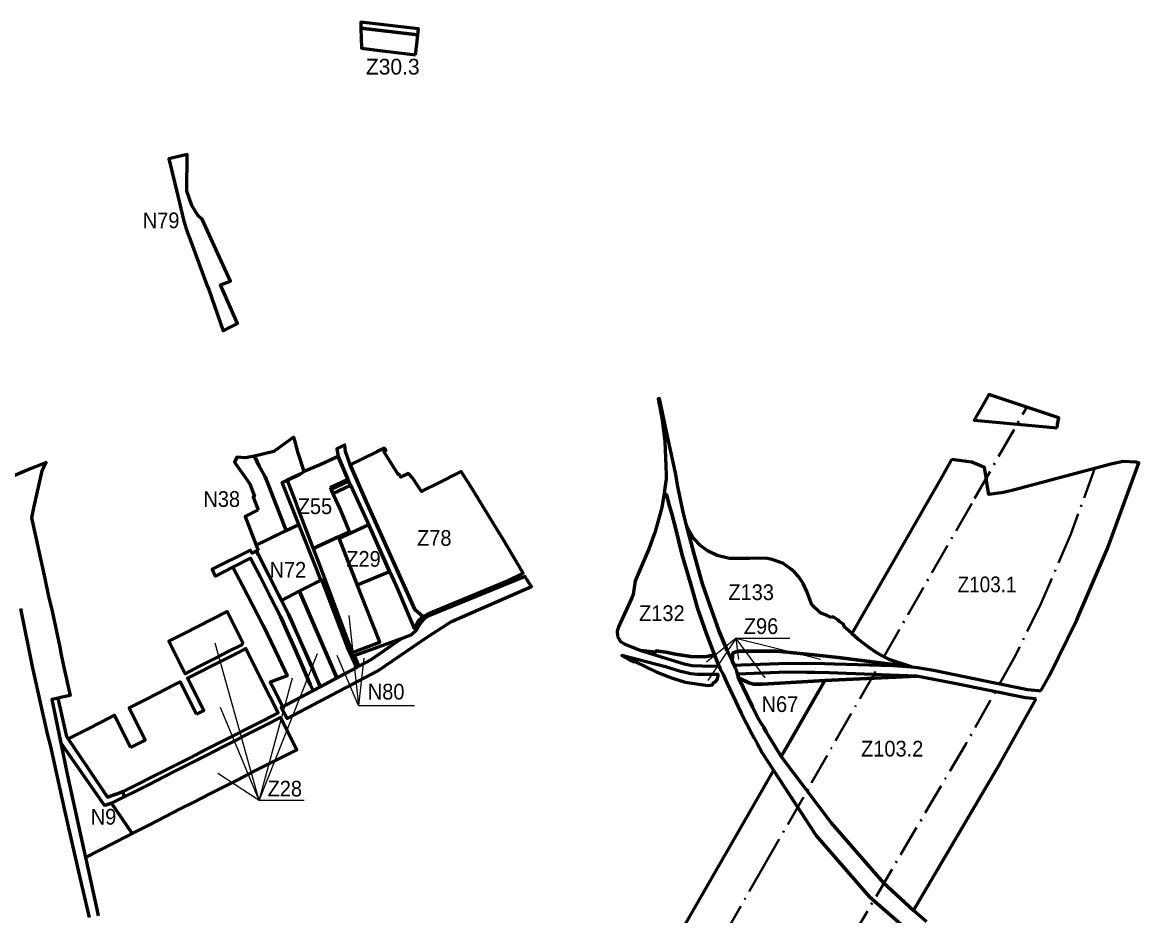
# Model space of a CAD drawing. Extents: x -650277 to -643422, y -1073980 to -1066720.
# Drawn here: x -648765 to -647061, y -1068122 to -1066758 of the extents above; entities that cross this region are included whole.
import ezdxf

# ---------------------------------------------------------------- set-up
doc = ezdxf.new("R2010")
doc.units = 0
doc.header["$LTSCALE"] = 9.6
doc.linetypes.add('DOT_DASHED', pattern=[7.7, 5, -1.2, 0.3, -1.2])
for name, color, linetype, lineweight in [('1', 7, 'Continuous', 60), ('15', 7, 'Continuous', 60), ('3', 7, 'Continuous', 60), ('40', 7, 'Continuous', 60), ('42', 7, 'Continuous', 60), ('45', 7, 'Continuous', 60), ('48', 7, 'Continuous', 60), ('60', 7, 'Continuous', 60), ('61', 7, 'Continuous', 60), ('62', 7, 'DOT_DASHED', 40), ('63', 7, 'Continuous', 25), ('7', 7, 'Continuous', 60), ('9', 7, 'Continuous', 60)]:
    doc.layers.add(name, color=color, linetype=linetype, lineweight=lineweight)

msp = doc.modelspace()

# ---------------------------------------------------------------- linework, layer by layer
at = {"layer": '1'}
msp.add_line((-648609.91, -1067940.58), (-648611.61, -1067932.63), dxfattribs=at)
for points in [[(-647708.71, -1067723.99), (-647721.05, -1067691.73), (-647734.63, -1067652.57), (-647744.61, -1067617.96), (-647758.25, -1067571.79), (-647768.5, -1067529.75), (-647773.96, -1067508.48), (-647777.55, -1067496.95), (-647781.85, -1067479.19), (-647785.64, -1067477.02), (-647789.39, -1067498.84), (-647792.54, -1067511.85), (-647799.39, -1067535.48)], [(-647704.458, -1067572.034), (-647719.661, -1067564.884), (-647729.802, -1067557.462), (-647740.124, -1067546.265), (-647751.41, -1067526.58), (-647740.49, -1067568.67), (-647727.37, -1067614.33), (-647715.92, -1067648.12), (-647702.04, -1067686.86), (-647690.09, -1067716.05), (-647681.91, -1067732.74), (-647680.804, -1067720.745), (-647672, -1067718), (-647643, -1067718), (-647614, -1067718), (-647557, -1067724), (-647520.145, -1067727.879), (-647408.2, -1067742.37)], [(-647799.39, -1067535.48), (-647808.71, -1067561.03), (-647817.59, -1067582.4)], [(-647591.227, -1067593.613), (-647604.415, -1067584.047), (-647606.559, -1067583.309), (-647620.586, -1067578.478), (-647628.441, -1067576.759), (-647640.087, -1067576.306), (-647654.743, -1067576.996), (-647685.968, -1067576.68), (-647704.458, -1067572.034)], [(-647817.59, -1067582.4), (-647829.97, -1067610.62), (-647832.8, -1067631.53), (-647835.06, -1067637.01), (-647855.24, -1067681.26), (-647857.51, -1067687.74), (-647856.9, -1067695.97)], [(-647573.605, -1067614.951), (-647580.539, -1067604.432), (-647586.864, -1067597.411), (-647591.227, -1067593.613)], [(-647530.82, -1067666.65), (-647536.83, -1067663.64), (-647547.663, -1067659.519), (-647560.187, -1067647.458), (-647567.744, -1067627.24), (-647573.605, -1067614.951)], [(-647499.095, -1067691.163), (-647503.97, -1067686.73), (-647510.6, -1067680.86), (-647511.24, -1067677.53), (-647517.74, -1067672.85), (-647520.13, -1067671.13), (-647527.76, -1067665.65), (-647530.82, -1067666.65)], [(-647856.9, -1067695.97), (-647852.3, -1067703.36), (-647845.74, -1067707.59), (-647821.02, -1067717.33)], [(-647474.13, -1067711.81), (-647489.3, -1067700.07), (-647499.095, -1067691.163)], [(-648399.64, -1067763.26), (-648424.14, -1067714.34), (-648435.34, -1067720.01), (-648446.58, -1067725.71), (-648468.97, -1067736.91), (-648480.06, -1067742.47), (-648491.14, -1067748.02), (-648513.23, -1067759.38), (-648488.49, -1067808.76), (-648499.7, -1067814.37)], [(-647453.87, -1067724.97), (-647462.45, -1067719.84), (-647474.13, -1067711.81)], [(-647821.02, -1067717.33), (-647798.5, -1067719.67), (-647798.17, -1067717.58), (-647783.13, -1067719.68), (-647768.53, -1067722.82), (-647745.41, -1067726.6), (-647732.71, -1067727.02), (-647720.45, -1067726.49), (-647708.71, -1067723.99)], [(-647408.2, -1067742.37), (-647440.81, -1067731.38), (-647453.87, -1067724.97)], [(-648611.61, -1067932.63), (-648547.09, -1067899.87), (-648530.81, -1067891.61), (-648508.22, -1067880.38), (-648486.09, -1067868.98), (-648463.91, -1067857.74), (-648441.47, -1067846.37), (-648419.44, -1067835.3), (-648397.04, -1067823.85), (-648374.84, -1067812.43), (-648399.64, -1067763.26)], [(-648499.7, -1067814.37), (-648524.44, -1067765.11), (-648535.61, -1067770.85), (-648557.84, -1067782.26), (-648580.14, -1067793.61), (-648602.3, -1067804.83), (-648577.78, -1067854.07), (-648600.14, -1067865.29)], [(-648600.14, -1067865.29), (-648624.76, -1067816.11), (-648645.11, -1067826.48), (-648668.085, -1067838.186), (-648675.26, -1067841.84), (-648695.27, -1067852.04), (-648664.41, -1067897.91)], [(-648572.5, -1067983.59), (-648546.76, -1067970.44), (-648524.72, -1067958.93), (-648502.59, -1067948), (-648480.12, -1067936.55), (-648457.87, -1067925.4), (-648435.55, -1067913.84), (-648413.41, -1067902.53), (-648402.29, -1067897.02), (-648391.08, -1067891.24), (-648368.78, -1067879.75), (-648346.57, -1067868.56), (-648371.27, -1067819.47), (-648393.35, -1067830.81), (-648415.69, -1067841.98), (-648426.65, -1067847.64), (-648437.89, -1067853.4), (-648460.33, -1067864.88), (-648482.5, -1067876.22), (-648504.92, -1067887.52), (-648527.33, -1067898.74), (-648549.44, -1067910.07), (-648571.88, -1067921.71), (-648591.04, -1067931.62), (-648609.91, -1067940.58)], [(-648664.41, -1067897.91), (-648635.249, -1067941.252), (-648620.658, -1067935.93), (-648611.61, -1067932.63)], [(-648609.91, -1067940.58), (-648629.22, -1067950.214), (-648597.93, -1067996.72), (-648572.5, -1067983.59)]]:
    msp.add_lwpolyline(points, dxfattribs=at)
for points in [[(-648254.04, -1067616.96), (-648204.88, -1067596.54), (-648236.549, -1067525.258), (-648263.7, -1067537.93), (-648281.774, -1067546.369)], [(-648397.98, -1067678.79), (-648373.99, -1067728.95), (-648361.08, -1067755.88), (-648387.04, -1067765.67), (-648384.25, -1067771.07), (-648367.811, -1067802.994), (-648321.623, -1067778.399), (-648326, -1067769), (-648337.32, -1067742.59), (-648348.55, -1067716.71), (-648359.6, -1067691.58), (-648371.34, -1067665.08), (-648386.91, -1067634.83), (-648402.02, -1067605.49), (-648417.12, -1067576.17), (-648443.83, -1067589.92), (-648428.7, -1067619.24), (-648413.57, -1067648.57)], [(-648342.697, -1067626.806), (-648369.949, -1067640.851), (-648359.213, -1067661.956), (-648310.511, -1067772.476), (-648285.254, -1067759.008), (-648296.891, -1067732.172), (-648342.023, -1067628.096)], [(-648519.63, -1067691.58), (-648541.86, -1067702.86), (-648516.73, -1067752.57), (-648494.84, -1067741.06), (-648472.5, -1067729.76), (-648450.23, -1067718.32), (-648430.17, -1067708.33), (-648428.67, -1067705.52), (-648452.72, -1067657.62)]]:
    msp.add_lwpolyline(points, close=True, dxfattribs=at)
at = {"layer": '1', "lineweight": 25}
msp.add_lwpolyline([(-648335, -1067946), (-648404, -1067946), (-648353, -1067759)], dxfattribs=at)
at = {"layer": '15'}
msp.add_line((-648264.34, -1067464.83), (-648267.21, -1067458.61), dxfattribs=at)
for points in [[(-648161.58, -1066777.41), (-648160.51, -1066768.4), (-648248.43, -1066758.34), (-648248.77, -1066767.43)], [(-648362.585, -1067534.204), (-648343.41, -1067524.81), (-648369.01, -1067460.52), (-648361, -1067457.36), (-648341.15, -1067448.14), (-648335.38, -1067444.07), (-648344.41, -1067416.04), (-648349.67, -1067396.88), (-648351.06, -1067391.62), (-648352.16, -1067392.42), (-648353.35, -1067393.29), (-648381.48, -1067413.68), (-648410.92, -1067420.63), (-648409.61, -1067423.44), (-648404.29, -1067434.9), (-648394.92, -1067452.23), (-648393.17, -1067455.88)], [(-648237.81, -1067522.42), (-648204.88, -1067596.54), (-648198.39, -1067610.97), (-648193.8, -1067621), (-648189.03, -1067631.71), (-648167.48, -1067683.45), (-648164.79, -1067678.96), (-648163.11, -1067676.17), (-648160.68, -1067671.55), (-648153.98, -1067665.43), (-648166.173, -1067654.853), (-648240.51, -1067489.9), (-648265.197, -1067434.03), (-648265.197, -1067434.03), (-648272.022, -1067413.59), (-648273.008, -1067403.338), (-648279.24, -1067406.38), (-648285.08, -1067409.24), (-648283.21, -1067420.88), (-648268.67, -1067455.43), (-648267.21, -1067458.61), (-648294.04, -1067471.35), (-648291.172, -1067477.571), (-648264.34, -1067464.83), (-648253.1, -1067489.23)], [(-648359.6, -1067691.58), (-648348.55, -1067716.71), (-648337.32, -1067742.59), (-648326, -1067769), (-648321.623, -1067778.399), (-648310.511, -1067772.476), (-648323.178, -1067741.953), (-648359.213, -1067661.956), (-648405.054, -1067571.837), (-648408.002, -1067565.219), (-648414.73, -1067568.8), (-648417.19, -1067564.02), (-648475.78, -1067593.11), (-648473.34, -1067598.06), (-648470.57, -1067603.69), (-648470.47, -1067603.64), (-648443.83, -1067589.92), (-648417.12, -1067576.17), (-648402.02, -1067605.49), (-648386.91, -1067634.83), (-648371.34, -1067665.08)], [(-647988.235, -1067619.912), (-647995.04, -1067608.56), (-647997.68, -1067604.11), (-648144.83, -1067664.48), (-648151.6, -1067668.12), (-648157.2, -1067674.32), (-648161, -1067680.96), (-648162.69, -1067684), (-648164.09, -1067686.51), (-648171.21, -1067693.37), (-648187.139, -1067699.179), (-648233.264, -1067731.288), (-648251.711, -1067741.124), (-648258.96, -1067725.37), (-648262.632, -1067726.711), (-648255.016, -1067742.886), (-648319.983, -1067777.526), (-648370.113, -1067804.22), (-648360.993, -1067821.027), (-648222.872, -1067748.412), (-648146.127, -1067695.8), (-648110.36, -1067673.133), (-647988.052, -1067619.624)]]:
    msp.add_lwpolyline(points, close=True, dxfattribs=at)
for points in [[(-648793.71, -1067456.88), (-648757.97, -1067441.51), (-648728.95, -1067430.33), (-648735.59, -1067442.88), (-648748.53, -1067499.3), (-648751.29, -1067514.57), (-648731.06, -1067607.06), (-648725.8, -1067632.36), (-648720.1, -1067657.12), (-648708.26, -1067712.07), (-648706.08, -1067723.56), (-648702.33, -1067740.84), (-648692.53, -1067785.79), (-648704.614, -1067788.491), (-648710.961, -1067789.906), (-648720.34, -1067792), (-648696.93, -1067905.76), (-648672.31, -1068017.25), (-648668.92, -1068032.96), (-648651.89, -1068111.95), (-648649.74, -1068121.95)], [(-648267.21, -1067458.61), (-648294.04, -1067471.35), (-648291.172, -1067477.571), (-648264.34, -1067464.83)], [(-648662.71, -1068124.76), (-648677.61, -1068061.74), (-648700.16, -1067963.42), (-648722.09, -1067863.84), (-648727.05, -1067844.33), (-648738.7, -1067792.04), (-648749.97, -1067741.49), (-648767.84, -1067652.98)], [(-648710.961, -1067789.906), (-648720.34, -1067792), (-648706.687, -1067858.345), (-648640, -1067954)], [(-648695.27, -1067852.04), (-648697.7, -1067848.43), (-648699.621, -1067840.06), (-648699.593, -1067840.046), (-648710.96, -1067789.91)], [(-648611.61, -1067932.63), (-648620.658, -1067935.93), (-648635.249, -1067941.252), (-648664.41, -1067897.91), (-648695.27, -1067852.04)], [(-648640, -1067954), (-648629.22, -1067950.214), (-648609.91, -1067940.58), (-648611.61, -1067932.63)]]:
    msp.add_lwpolyline(points, dxfattribs=at)
at = {"layer": '3'}
msp.add_lwpolyline([(-648165.33, -1066807.74), (-648162.8, -1066786.8), (-648161.58, -1066777.41), (-648248.77, -1066767.43), (-648247.78, -1066797.53), (-648211.58, -1066802.18)], close=True, dxfattribs=at)
at = {"layer": '40'}
msp.add_lwpolyline([(-648405.27, -1067502.27), (-648425.5, -1067512.73), (-648408.26, -1067556.58), (-648362.585, -1067534.205), (-648393.17, -1067455.88), (-648394.92, -1067452.23), (-648404.29, -1067434.9), (-648410.92, -1067420.63), (-648425, -1067423.05), (-648437.75, -1067421.99), (-648441.48, -1067429.63), (-648430.4, -1067445.51), (-648418.3, -1067462.86), (-648412.46, -1067477.42), (-648411.25, -1067481.73), (-648412.89, -1067482.55)], close=True, dxfattribs=at)
at = {"layer": '42'}
msp.add_lwpolyline([(-647606.818, -1067879.061), (-647540.208, -1067762.876), (-647635.758, -1067768.38), (-647649.22, -1067768.38), (-647656.469, -1067766.309), (-647672.05, -1067758.98), (-647650.8, -1067803.28), (-647642.29, -1067820.76), (-647637.21, -1067829.29), (-647633.69, -1067834.31), (-647630.3, -1067841.02), (-647625.37, -1067848.86), (-647617.25, -1067861.95)], close=True, dxfattribs=at)
at = {"layer": '45'}
msp.add_lwpolyline([(-648405.41, -1067563.84), (-648408.002, -1067565.219), (-648369.949, -1067640.851), (-648342.697, -1067626.806), (-648328.54, -1067619.51), (-648309.522, -1067609.713), (-648317.43, -1067590), (-648343.41, -1067524.81), (-648408.26, -1067556.58)], close=True, dxfattribs=at)
at = {"layer": '48'}
for points in [[(-648528.01, -1067023.13), (-648518.72, -1067061.99), (-648514.86, -1067074.83), (-648507.88, -1067093.9), (-648483.31, -1067160.63), (-648480.57, -1067166.13), (-648458.73, -1067229.1), (-648449.03, -1067224.14), (-648437.02, -1067217.99), (-648462.97, -1067159.24), (-648447.66, -1067153.25), (-648467.56, -1067110.02), (-648490.23, -1067060.06), (-648496.87, -1067053.5), (-648506.78, -1067037.81), (-648514.38, -1067016.2), (-648513.842, -1066960.243), (-648541.52, -1066966.657)], [(-648342.023, -1067628.096), (-648296.891, -1067732.172), (-648285.254, -1067759.008), (-648255.016, -1067742.886), (-648265.614, -1067720.378), (-648269.27, -1067712.6), (-648308.43, -1067609.15), (-648328.54, -1067619.51), (-648342.697, -1067626.806)], [(-648258.96, -1067725.37), (-648251.711, -1067741.124), (-648233.264, -1067731.288), (-648187.139, -1067699.179)]]:
    msp.add_lwpolyline(points, close=True, dxfattribs=at)
for points in [[(-648295.409, -1067468.129), (-648268.67, -1067455.43), (-648283.21, -1067420.88), (-648295.66, -1067426.76), (-648309.57, -1067433.34), (-648335.38, -1067444.07), (-648341.15, -1067448.14), (-648361, -1067457.36), (-648347.51, -1067492.87), (-648346.27, -1067496.14)], [(-648346.27, -1067496.14), (-648334.09, -1067528.2), (-648321.36, -1067561.69), (-648282.863, -1067543.596), (-648265.757, -1067535.555), (-648279.86, -1067502.11), (-648294.04, -1067471.35), (-648295.409, -1067468.129)], [(-648265.08, -1067712.06), (-648261.25, -1067720.39), (-648235.78, -1067710.79), (-648219.86, -1067704.42), (-648247.53, -1067633.53), (-648254.04, -1067616.96), (-648282.863, -1067543.596), (-648321.36, -1067561.69)], [(-648321.361, -1067561.69), (-648311.95, -1067586.45), (-648265.08, -1067712.06)]]:
    msp.add_lwpolyline(points, dxfattribs=at)
at = {"layer": '60'}
for points in [[(-647606.818, -1067879.061), (-647617.25, -1067861.95), (-647625.37, -1067848.86), (-647630.3, -1067841.02), (-647633.69, -1067834.31), (-647637.21, -1067829.29), (-647642.29, -1067820.76), (-647650.8, -1067803.28), (-647672.05, -1067758.98), (-647673.47, -1067753.48), (-647673.47, -1067753.48), (-647674.67, -1067748.73), (-647676.47, -1067744.5), (-647678.66, -1067739.38), (-647681.91, -1067732.74), (-647690.09, -1067716.05), (-647702.04, -1067686.86), (-647715.92, -1067648.12), (-647727.37, -1067614.33), (-647740.49, -1067568.67), (-647751.41, -1067526.58), (-647756.55, -1067505.32), (-647759.16, -1067494.01), (-647764.89, -1067466.64), (-647768.5, -1067446.04), (-647778.78, -1067397.1), (-647792.52, -1067332.74), (-647794.54, -1067333.14), (-647788.77, -1067365.03), (-647784.55, -1067398.01), (-647782.39, -1067448.34), (-647782.5, -1067455.11), (-647784.36, -1067469.6), (-647785.64, -1067477.02), (-647781.85, -1067479.19), (-647777.55, -1067496.95), (-647773.96, -1067508.48), (-647768.5, -1067529.75), (-647758.25, -1067571.79), (-647744.61, -1067617.96), (-647734.63, -1067652.57), (-647721.05, -1067691.73), (-647708.71, -1067723.99), (-647702.21, -1067740.43), (-647699.89, -1067745.24), (-647697.85, -1067749.46), (-647695.71, -1067753.9), (-647690.19, -1067766.37), (-647668.13, -1067812.76), (-647651.94, -1067844.36), (-647648.33, -1067851.17), (-647643.83, -1067859.13), (-647635.77, -1067873.43), (-647618.773, -1067899.914)], [(-647783.54, -1067742.11), (-647850.45, -1067724.77), (-647838.18, -1067731.62), (-647832.56, -1067734.22), (-647829.49, -1067734.58), (-647796.87, -1067750.25), (-647774.54, -1067758.68), (-647753.53, -1067765.58), (-647718.54, -1067770.6), (-647712.01, -1067769.63), (-647712.26, -1067767.28)], [(-647712.26, -1067767.28), (-647711.773, -1067767.135), (-647711.286, -1067766.968), (-647710.799, -1067766.777), (-647710.315, -1067766.562), (-647709.834, -1067766.324), (-647709.359, -1067766.062), (-647708.892, -1067765.776), (-647708.433, -1067765.466), (-647707.985, -1067765.133), (-647707.55, -1067764.777), (-647707.128, -1067764.398), (-647706.723, -1067763.999), (-647706.335, -1067763.579), (-647705.966, -1067763.14), (-647705.617, -1067762.683), (-647705.29, -1067762.21), (-647704.985, -1067761.721), (-647704.704, -1067761.22), (-647704.447, -1067760.707), (-647704.216, -1067760.184), (-647704.01, -1067759.653), (-647703.83, -1067759.117), (-647703.675, -1067758.576), (-647703.547, -1067758.033), (-647703.445, -1067757.489), (-647703.368, -1067756.946), (-647703.315, -1067756.406), (-647703.287, -1067755.87), (-647703.282, -1067755.341), (-647703.3, -1067754.818), (-647703.34, -1067754.304), (-647703.4, -1067753.8), (-647711.09, -1067753.71), (-647728.98, -1067754.07), (-647734.69, -1067753.66), (-647744.74, -1067752.93), (-647757.74, -1067749.96), (-647759.13, -1067749.54), (-647783.54, -1067742.11)], [(-647405.026, -1068113.904), (-647451.024, -1068071.886), (-647530.038, -1067980.839), (-647606.818, -1067879.061)], [(-647618.773, -1067899.914), (-647553.628, -1067999.427), (-647472.338, -1068093.096), (-647419.713, -1068138.871)], [(-647385.13, -1068131.51), (-647405.026, -1068113.904)]]:
    msp.add_lwpolyline(points, dxfattribs=at)
for points in [[(-647754.88, -1067737.59), (-647743.12, -1067739.93), (-647728.29, -1067740.64), (-647713.15, -1067741), (-647702.21, -1067740.43), (-647708.71, -1067723.99), (-647720.45, -1067726.49), (-647732.71, -1067727.02), (-647745.41, -1067726.6), (-647768.53, -1067722.82), (-647783.13, -1067719.68), (-647798.17, -1067717.58), (-647798.5, -1067719.67), (-647821.02, -1067717.33)], [(-647596.91, -1067736.61), (-647572.33, -1067737.03), (-647555.58, -1067736.71), (-647525.685, -1067737.542), (-647436.72, -1067740.02), (-647408.2, -1067742.37), (-647520.145, -1067727.879), (-647557, -1067724), (-647614, -1067718), (-647643, -1067718), (-647672, -1067718), (-647680.804, -1067720.745), (-647681.91, -1067732.74), (-647678.66, -1067739.38), (-647678.66, -1067739.38), (-647667.76, -1067739.01), (-647638.75, -1067738.03)], [(-647540.208, -1067762.876), (-647400.63, -1067756.19), (-647533.597, -1067751.344), (-647555.67, -1067750.91), (-647568.36, -1067750.7), (-647597.83, -1067750.21), (-647673.47, -1067753.48), (-647672.05, -1067758.98), (-647672.05, -1067758.98), (-647656.469, -1067766.309), (-647649.22, -1067768.38), (-647635.758, -1067768.38)]]:
    msp.add_lwpolyline(points, close=True, dxfattribs=at)
at = {"layer": '61'}
msp.add_lwpolyline([(-647185.93, -1067377.38), (-647184.97, -1067372.22), (-647183.09, -1067362.16), (-647289.924, -1067326.309), (-647312.383, -1067365.484)], close=True, dxfattribs=at)
for points in [[(-647346.944, -1067425.768), (-647364.024, -1067455.561), (-647499.095, -1067691.163), (-647489.3, -1067700.07)], [(-647243.39, -1067469.81), (-647252.99, -1067472.35), (-647267.49, -1067476.23), (-647290.23, -1067478.89), (-647292.51, -1067464.56), (-647294.31, -1067453.26), (-647296.75, -1067437.91), (-647315.89, -1067429.71), (-647346.944, -1067425.768)], [(-647061.252, -1067430.908), (-647061.252, -1067430.908), (-647063.45, -1067430.19), (-647064.87, -1067429.73), (-647084.77, -1067428.64), (-647103.55, -1067432.54), (-647243.39, -1067469.81)], [(-647210.537, -1067778.594), (-647198.088, -1067756.5), (-647155.592, -1067670.17), (-647108.971, -1067561.55), (-647061.252, -1067430.908)], [(-647489.3, -1067700.07), (-647474.13, -1067711.81), (-647462.45, -1067719.84), (-647453.87, -1067724.97), (-647440.81, -1067731.38), (-647408.2, -1067742.37), (-647398.74, -1067743.15), (-647374.55, -1067747.34)], [(-647374.55, -1067747.34), (-647280.78, -1067766.44), (-647237.91, -1067775.18), (-647231.17, -1067776.55), (-647213.92, -1067778.26), (-647210.537, -1067778.594)], [(-647400.63, -1067756.19), (-647540.208, -1067762.876), (-647593.267, -1067855.425), (-647606.818, -1067879.061)], [(-647217.611, -1067791.149), (-647233.83, -1067789.69), (-647345.11, -1067767.28), (-647400.63, -1067756.19)], [(-647405.026, -1068113.904), (-647273.297, -1067889.981), (-647217.611, -1067791.149)], [(-647606.818, -1067879.061), (-647530.038, -1067980.839), (-647451.024, -1068071.886), (-647405.026, -1068113.904)], [(-647464.94, -1068215.752), (-647461.188, -1068209.373), (-647419.713, -1068138.871), (-647472.338, -1068093.096), (-647553.628, -1067999.427), (-647618.773, -1067899.914), (-647685.819, -1068016.861)], [(-647685.819, -1068016.861), (-647781.346, -1068183.485), (-647791.055, -1068200.507)]]:
    msp.add_lwpolyline(points, dxfattribs=at)
at = {"layer": '62'}
for points in [[(-647729.261, -1068213.27), (-647633.767, -1068046.703), (-647560.654, -1067919.174), (-647311.972, -1067485.403), (-647231.921, -1067345.773)], [(-647128.118, -1067439.088), (-647164.761, -1067539.408), (-647210.113, -1067645.071), (-647251.182, -1067728.502), (-647325.296, -1067860.04), (-647512.903, -1068178.95), (-647726.877, -1068542.68), (-647850.594, -1068756.441), (-647875.691, -1068807.609), (-647903.473, -1068876.174), (-647924.037, -1068940.973), (-647945.559, -1069039.601), (-647956.348, -1069145.994), (-647956.677, -1069214.977), (-647954.925, -1069248.93), (-647950.785, -1069292.731), (-647945.699, -1069329.377), (-647937.748, -1069374.683)]]:
    msp.add_lwpolyline(points, dxfattribs=at)
at = {"layer": '63'}
for p, q in [((-648404, -1067946), (-648471, -1067706)), ((-647676, -1067699), (-647672, -1067731)), ((-647676, -1067699), (-647632, -1067759)), ((-648404, -1067946), (-648315, -1067722)), ((-648404, -1067946), (-648463, -1067804))]:
    msp.add_line(p, q, dxfattribs=at)
for points in [[(-648267, -1067664), (-648252, -1067801), (-648285, -1067725)], [(-647594, -1067699), (-647676, -1067699), (-647721, -1067735)], [(-647547, -1067731), (-647676, -1067699), (-647719, -1067763)], [(-648244, -1067729), (-648252, -1067801), (-648167, -1067801)], [(-648335, -1067946), (-648404, -1067946), (-648467, -1067905)]]:
    msp.add_lwpolyline(points, dxfattribs=at)
at = {"layer": '7'}
msp.add_lwpolyline([(-648640, -1067954), (-648706.687, -1067858.345), (-648696.93, -1067905.76), (-648668.92, -1068032.96), (-648605.323, -1068000.463), (-648597.93, -1067996.72), (-648629.22, -1067950.214)], close=True, dxfattribs=at)
at = {"layer": '9'}
msp.add_lwpolyline([(-648153.98, -1067665.43), (-648149.933, -1067663.646), (-648146.21, -1067661.3), (-648023.96, -1067610.13), (-648000.63, -1067599.14), (-648031.77, -1067546.6), (-648045.04, -1067525.15), (-648076.32, -1067474.6), (-648081.31, -1067466.54), (-648095.28, -1067444.06), (-648133.56, -1067463.2), (-648150.46, -1067471.66), (-648155.85, -1067474.35), (-648164.24, -1067462.15), (-648166.97, -1067458.18), (-648170.38, -1067453.23), (-648175.94, -1067446.89), (-648187.44, -1067452.8), (-648190.23, -1067447.83), (-648191.46, -1067448.59), (-648213.34, -1067413.46), (-648210.48, -1067411.68), (-648211.08, -1067410.6), (-648212.32, -1067408.39), (-648224.19, -1067414.14), (-648265.197, -1067434.03), (-648240.51, -1067489.9), (-648240.51, -1067489.9), (-648166.173, -1067654.853)], close=True, dxfattribs=at)

# ---------------------------------------------------------------- texts
at = {"layer": '1', "width": 0.95}
for s, p in [('Z29', (-648270.915, -1067589.341)), ('Z133', (-647687.579, -1067640.215)), ('Z132', (-647823.879, -1067672.215)), ('Z28', (-648391, -1067940))]:
    msp.add_text(s, height=24, dxfattribs=at).set_placement(p)
at = {"layer": '63'}
msp.add_text('Z30.3', height=24, dxfattribs=at).set_placement((-648241, -1066838))
for s, width, p in [('N79', 0.95, (-648581.544, -1067072.648)), ('N38', 0.95, (-648489, -1067498)), ('Z55', 0.95, (-648345, -1067509)), ('Z78', 0.95, (-648162.836, -1067557.421)), ('N72', 0.95, (-648388, -1067606)), ('Z103.1', 0.9, (-647337.666, -1067628.26)), ('Z96', 0.95, (-647664, -1067692)), ('N80', 0.95, (-648238, -1067792)), ('N67', 0.95, (-647636.885, -1067811.038)), ('Z103.2', 0.95, (-647485, -1067879)), ('N9', 0.95, (-648661, -1067983))]:
    msp.add_text(s, height=24, dxfattribs=dict(at, width=width)).set_placement(p)

doc.saveas('drawing.dxf')
